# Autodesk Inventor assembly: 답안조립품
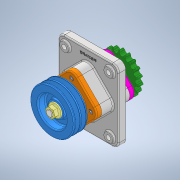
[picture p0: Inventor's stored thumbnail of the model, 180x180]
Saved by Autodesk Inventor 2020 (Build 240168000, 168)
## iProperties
Created: 2021-07
Part Number: 답안조립품
Document SubType Name: Assembly
Designer: Owner
Author: Owner
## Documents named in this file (16)
- C:\Users\Owner\Desktop\710707V1006\답안조립품.iam
- C:\Users\Owner\Desktop\710707V1006\본체.ipt
- C:\Users\Owner\Desktop\710707V1006\M16 너트.ipt
- C:\Users\Owner\Desktop\710707V1006\V-벨트풀리.ipt
- C:\Users\Owner\Desktop\710707V1006\멈춤나사 M4.ipt
- C:\Users\Owner\Desktop\710707V1006\베어링 6206.ipt
- C:\Users\Owner\Desktop\710707V1006\볼트 M6.ipt
- C:\Users\Owner\Desktop\710707V1006\부시.ipt
- C:\Users\Owner\Desktop\710707V1006\오일실 30x42x8.ipt
- C:\Users\Owner\Desktop\710707V1006\오일실 30x45x8.ipt
- C:\Users\Owner\Desktop\710707V1006\체인 스프로킷.ipt
- C:\Users\Owner\Desktop\710707V1006\축.ipt
- C:\Users\Owner\Desktop\710707V1006\커버A.ipt
- C:\Users\Owner\Desktop\710707V1006\커버B.ipt
- C:\Users\Owner\Desktop\710707V1006\키 6x6x18.ipt
- C:\Users\Owner\Desktop\710707V1006\키 6x6x20.ipt
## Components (3 placed, 2 different names)
1. M16 너트:1 — 각도:5
2. V-벨트풀리:1 — 각도:1, 각도:6
3. M16 너트:2 — 각도:3, 각도:4
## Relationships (5: Angle 5)
- 각도:1 [Angle]: V-벨트풀리:1
- 각도:3 [Angle]: M16 너트:2
- 각도:4 [Angle]: M16 너트:2
- 각도:5 [Angle]: M16 너트:1
- 각도:6 [Angle]: V-벨트풀리:1
